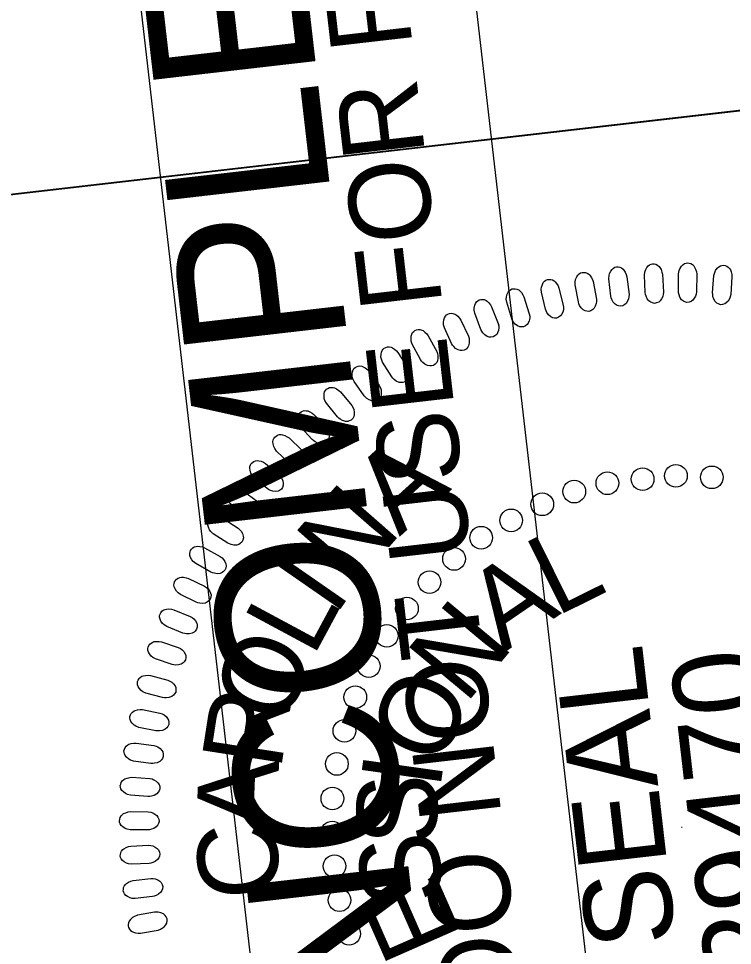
# Model space of a CAD drawing. Extents: x 477607 to 479438, y 495543 to 499482.
# Drawn here: x 477704.9 to 477755.3, y 497250.4 to 497316 of the extents above; entities that cross this region are included whole.
import ezdxf

# ---------------------------------------------------------------- set-up
doc = ezdxf.new("R2010")
doc.units = 0
for name, color, linetype in [('Sheet Border Standard 30in CELL', 7, 'Continuous'), ('Sheet PE Seal Cell', 7, 'Continuous'), ('Sheet Plan CELL', 7, 'Continuous'), ('Sheet Sticker Incomplete CELL', 7, 'Continuous')]:
    doc.layers.add(name, color=color, linetype=linetype)

msp = doc.modelspace()

# ---------------------------------------------------------------- linework, layer by layer
at = {"layer": 'Sheet Border Standard 30in CELL'}
msp.add_line((477682.369, 497301.002), (477794.079, 497313.883), dxfattribs=at)
for points in [[(477682.369, 497301.002), (477670.914, 497400.344), (477782.674, 497413.23), (477794.128, 497313.888)], [(477693.829, 497201.611), (477682.369, 497301.002), (477794.128, 497313.888), (477805.588, 497214.497)]]:
    msp.add_lwpolyline(points, close=True, dxfattribs=at)
at = {"layer": 'Sheet PE Seal Cell'}
msp.add_line((477751.702, 497258.805), (477751.748, 497258.81), dxfattribs=at)
for points in [[(477749.145, 497296.61), (477749.081, 497297.835), (477749.107, 497298.055), (477749.152, 497298.198), (477749.255, 497298.373), (477749.347, 497298.488), (477749.454, 497298.573), (477749.557, 497298.618), (477749.668, 497298.644), (477749.781, 497298.629), (477749.902, 497298.606), (477750.009, 497298.552), (477750.119, 497298.457), (477750.183, 497298.381), (477750.258, 497298.235), (477750.327, 497298.058), (477750.358, 497297.9), (477750.43, 497296.646), (477750.416, 497296.476), (477750.378, 497296.334), (477750.297, 497296.17), (477750.192, 497296.025), (477750.1, 497295.94), (477749.946, 497295.872), (477749.797, 497295.844), (477749.646, 497295.877), (477749.539, 497295.921), (477749.407, 497296.014), (477749.279, 497296.177), (477749.202, 497296.353), (477749.166, 497296.48)], [(477751.488, 497296.712), (477751.502, 497297.939), (477751.542, 497298.158), (477751.595, 497298.297), (477751.709, 497298.466), (477751.808, 497298.574), (477751.921, 497298.652), (477752.025, 497298.691), (477752.139, 497298.709), (477752.25, 497298.688), (477752.369, 497298.657), (477752.473, 497298.596), (477752.577, 497298.495), (477752.635, 497298.415), (477752.701, 497298.264), (477752.759, 497298.085), (477752.78, 497297.925), (477752.773, 497296.668), (477752.749, 497296.498), (477752.702, 497296.359), (477752.611, 497296.201), (477752.497, 497296.063), (477752.399, 497295.984), (477752.241, 497295.926), (477752.092, 497295.908), (477751.942, 497295.95), (477751.838, 497296), (477751.712, 497296.101), (477751.595, 497296.272), (477751.529, 497296.453), (477751.502, 497296.582)], [(477753.905, 497296.591), (477753.996, 497297.814), (477754.049, 497298.03), (477754.111, 497298.166), (477754.236, 497298.327), (477754.341, 497298.429), (477754.459, 497298.5), (477754.566, 497298.532), (477754.679, 497298.544), (477754.789, 497298.516), (477754.907, 497298.477), (477755.007, 497298.41), (477755.103, 497298.302), (477755.157, 497298.218), (477755.213, 497298.064), (477755.26, 497297.881), (477755.27, 497297.72), (477755.185, 497296.467), (477755.15, 497296.299), (477755.095, 497296.163), (477754.993, 497296.011), (477754.871, 497295.88), (477754.769, 497295.807), (477754.608, 497295.759), (477754.457, 497295.75), (477754.311, 497295.801), (477754.21, 497295.859), (477754.091, 497295.967), (477753.984, 497296.145), (477753.93, 497296.33), (477753.911, 497296.461)], [(477744.418, 497295.948), (477744.202, 497297.155), (477744.201, 497297.378), (477744.226, 497297.524), (477744.307, 497297.711), (477744.383, 497297.836), (477744.48, 497297.934), (477744.576, 497297.992), (477744.683, 497298.031), (477744.797, 497298.032), (477744.92, 497298.023), (477745.033, 497297.983), (477745.154, 497297.903), (477745.227, 497297.835), (477745.32, 497297.7), (477745.41, 497297.533), (477745.46, 497297.381), (477745.689, 497296.145), (477745.697, 497295.974), (477745.677, 497295.829), (477745.617, 497295.656), (477745.531, 497295.499), (477745.45, 497295.403), (477745.306, 497295.316), (477745.162, 497295.27), (477745.008, 497295.283), (477744.896, 497295.314), (477744.753, 497295.39), (477744.606, 497295.535), (477744.508, 497295.7), (477744.456, 497295.823)], [(477746.716, 497296.363), (477746.576, 497297.582), (477746.588, 497297.804), (477746.624, 497297.948), (477746.716, 497298.13), (477746.8, 497298.25), (477746.903, 497298.342), (477747.001, 497298.393), (477747.111, 497298.426), (477747.225, 497298.419), (477747.347, 497298.403), (477747.457, 497298.355), (477747.573, 497298.268), (477747.641, 497298.196), (477747.726, 497298.055), (477747.806, 497297.883), (477747.846, 497297.728), (477747.997, 497296.48), (477747.994, 497296.309), (477747.965, 497296.165), (477747.894, 497295.996), (477747.799, 497295.845), (477747.712, 497295.754), (477747.562, 497295.677), (477747.416, 497295.64), (477747.263, 497295.663), (477747.154, 497295.701), (477747.016, 497295.785), (477746.878, 497295.94), (477746.79, 497296.11), (477746.746, 497296.236)], [(477742.097, 497295.435), (477741.806, 497296.627), (477741.789, 497296.848), (477741.807, 497296.997), (477741.875, 497297.188), (477741.943, 497297.318), (477742.033, 497297.422), (477742.125, 497297.486), (477742.23, 497297.531), (477742.343, 497297.539), (477742.467, 497297.538), (477742.583, 497297.505), (477742.708, 497297.433), (477742.785, 497297.37), (477742.886, 497297.24), (477742.987, 497297.08), (477743.047, 497296.93), (477743.353, 497295.711), (477743.371, 497295.542), (477743.361, 497295.395), (477743.312, 497295.219), (477743.236, 497295.057), (477743.16, 497294.956), (477743.023, 497294.86), (477742.881, 497294.806), (477742.727, 497294.809), (477742.614, 497294.833), (477742.466, 497294.899), (477742.31, 497295.035), (477742.202, 497295.194), (477742.142, 497295.313)], [(477739.719, 497294.76), (477739.354, 497295.931), (477739.324, 497296.151), (477739.331, 497296.3), (477739.388, 497296.496), (477739.448, 497296.629), (477739.531, 497296.739), (477739.619, 497296.808), (477739.72, 497296.861), (477739.833, 497296.875), (477739.957, 497296.882), (477740.074, 497296.856), (477740.204, 497296.792), (477740.285, 497296.734), (477740.394, 497296.611), (477740.504, 497296.458), (477740.573, 497296.312), (477740.955, 497295.115), (477740.984, 497294.946), (477740.983, 497294.8), (477740.945, 497294.621), (477740.88, 497294.454), (477740.811, 497294.349), (477740.679, 497294.245), (477740.542, 497294.182), (477740.388, 497294.175), (477740.273, 497294.191), (477740.122, 497294.248), (477739.958, 497294.375), (477739.839, 497294.526), (477739.772, 497294.641)], [(477737.538, 497293.996), (477737.1, 497295.141), (477737.056, 497295.359), (477737.055, 497295.508), (477737.099, 497295.707), (477737.15, 497295.844), (477737.227, 497295.959), (477737.31, 497296.033), (477737.408, 497296.092), (477737.519, 497296.114), (477737.642, 497296.128), (477737.76, 497296.11), (477737.894, 497296.054), (477737.979, 497296.001), (477738.095, 497295.885), (477738.215, 497295.739), (477738.293, 497295.598), (477738.749, 497294.428), (477738.789, 497294.261), (477738.797, 497294.115), (477738.771, 497293.934), (477738.716, 497293.763), (477738.654, 497293.654), (477738.529, 497293.542), (477738.396, 497293.47), (477738.242, 497293.454), (477738.127, 497293.463), (477737.972, 497293.51), (477737.8, 497293.626), (477737.673, 497293.77), (477737.599, 497293.88)], [(477735.465, 497293.006), (477734.955, 497294.123), (477734.898, 497294.338), (477734.887, 497294.487), (477734.919, 497294.687), (477734.961, 497294.827), (477735.03, 497294.947), (477735.109, 497295.026), (477735.203, 497295.091), (477735.313, 497295.119), (477735.434, 497295.142), (477735.554, 497295.131), (477735.691, 497295.084), (477735.778, 497295.036), (477735.902, 497294.928), (477736.031, 497294.79), (477736.118, 497294.654), (477736.647, 497293.514), (477736.697, 497293.351), (477736.713, 497293.205), (477736.698, 497293.023), (477736.655, 497292.849), (477736.599, 497292.736), (477736.482, 497292.616), (477736.354, 497292.536), (477736.201, 497292.51), (477736.086, 497292.512), (477735.928, 497292.55), (477735.749, 497292.654), (477735.613, 497292.79), (477735.532, 497292.895)], [(477733.266, 497291.873), (477732.687, 497292.955), (477732.617, 497293.166), (477732.596, 497293.313), (477732.615, 497293.516), (477732.65, 497293.659), (477732.711, 497293.782), (477732.784, 497293.866), (477732.874, 497293.937), (477732.982, 497293.972), (477733.102, 497294.002), (477733.221, 497293.999), (477733.361, 497293.96), (477733.452, 497293.918), (477733.582, 497293.818), (477733.719, 497293.688), (477733.814, 497293.558), (477734.414, 497292.453), (477734.474, 497292.294), (477734.5, 497292.149), (477734.496, 497291.966), (477734.464, 497291.79), (477734.415, 497291.674), (477734.305, 497291.547), (477734.182, 497291.459), (477734.032, 497291.424), (477733.916, 497291.418), (477733.757, 497291.446), (477733.572, 497291.539), (477733.428, 497291.666), (477733.34, 497291.766)], [(477731.231, 497290.653), (477730.585, 497291.696), (477730.502, 497291.902), (477730.472, 497292.048), (477730.479, 497292.251), (477730.504, 497292.396), (477730.557, 497292.523), (477730.625, 497292.612), (477730.71, 497292.688), (477730.816, 497292.73), (477730.934, 497292.767), (477731.054, 497292.772), (477731.195, 497292.742), (477731.288, 497292.705), (477731.424, 497292.613), (477731.569, 497292.492), (477731.672, 497292.368), (477732.34, 497291.304), (477732.41, 497291.148), (477732.446, 497291.005), (477732.453, 497290.823), (477732.431, 497290.645), (477732.391, 497290.526), (477732.289, 497290.392), (477732.172, 497290.297), (477732.024, 497290.252), (477731.909, 497290.24), (477731.748, 497290.257), (477731.557, 497290.339), (477731.405, 497290.456), (477731.312, 497290.551)], [(477729.289, 497289.314), (477728.579, 497290.315), (477728.483, 497290.515), (477728.444, 497290.659), (477728.437, 497290.862), (477728.453, 497291.008), (477728.499, 497291.138), (477728.561, 497291.231), (477728.641, 497291.312), (477728.744, 497291.361), (477728.859, 497291.405), (477728.978, 497291.418), (477729.122, 497291.397), (477729.216, 497291.366), (477729.358, 497291.283), (477729.51, 497291.171), (477729.621, 497291.054), (477730.354, 497290.034), (477730.434, 497289.882), (477730.479, 497289.742), (477730.497, 497289.56), (477730.487, 497289.382), (477730.454, 497289.26), (477730.361, 497289.121), (477730.25, 497289.018), (477730.106, 497288.964), (477729.991, 497288.944), (477729.83, 497288.952), (477729.634, 497289.021), (477729.475, 497289.129), (477729.375, 497289.217)], [(477727.397, 497287.827), (477726.625, 497288.78), (477726.516, 497288.975), (477726.469, 497289.116), (477726.45, 497289.318), (477726.456, 497289.465), (477726.493, 497289.597), (477726.55, 497289.694), (477726.624, 497289.78), (477726.724, 497289.835), (477726.836, 497289.887), (477726.955, 497289.906), (477727.099, 497289.894), (477727.196, 497289.87), (477727.343, 497289.796), (477727.502, 497289.694), (477727.619, 497289.584), (477728.415, 497288.612), (477728.504, 497288.466), (477728.557, 497288.329), (477728.588, 497288.148), (477728.588, 497287.969), (477728.563, 497287.846), (477728.479, 497287.701), (477728.375, 497287.592), (477728.234, 497287.529), (477728.121, 497287.502), (477727.959, 497287.499), (477727.76, 497287.556), (477727.594, 497287.653), (477727.49, 497287.735)], [(477725.624, 497286.212), (477724.795, 497287.116), (477724.674, 497287.303), (477724.617, 497287.441), (477724.585, 497287.642), (477724.583, 497287.788), (477724.611, 497287.922), (477724.662, 497288.023), (477724.731, 497288.114), (477724.827, 497288.175), (477724.935, 497288.233), (477725.052, 497288.26), (477725.197, 497288.257), (477725.295, 497288.239), (477725.446, 497288.174), (477725.611, 497288.083), (477725.736, 497287.981), (477726.591, 497287.06), (477726.689, 497286.92), (477726.751, 497286.786), (477726.793, 497286.609), (477726.804, 497286.43), (477726.787, 497286.305), (477726.712, 497286.155), (477726.615, 497286.039), (477726.478, 497285.967), (477726.367, 497285.934), (477726.206, 497285.921), (477726.003, 497285.965), (477725.832, 497286.051), (477725.722, 497286.127)], [(477723.981, 497284.553), (477723.096, 497285.402), (477722.964, 497285.582), (477722.899, 497285.716), (477722.855, 497285.914), (477722.843, 497286.061), (477722.863, 497286.197), (477722.907, 497286.3), (477722.97, 497286.395), (477723.062, 497286.462), (477723.167, 497286.527), (477723.282, 497286.561), (477723.426, 497286.567), (477723.526, 497286.555), (477723.68, 497286.5), (477723.85, 497286.419), (477723.981, 497286.325), (477724.893, 497285.459), (477725, 497285.326), (477725.069, 497285.197), (477725.122, 497285.022), (477725.145, 497284.844), (477725.136, 497284.718), (477725.07, 497284.564), (477724.981, 497284.442), (477724.849, 497284.362), (477724.74, 497284.321), (477724.58, 497284.299), (477724.375, 497284.33), (477724.199, 497284.406), (477724.085, 497284.474)], [(477722.431, 497282.751), (477721.494, 497283.544), (477721.351, 497283.714), (477721.278, 497283.844), (477721.221, 497284.039), (477721.2, 497284.184), (477721.212, 497284.321), (477721.249, 497284.427), (477721.306, 497284.526), (477721.394, 497284.598), (477721.494, 497284.671), (477721.607, 497284.712), (477721.751, 497284.727), (477721.85, 497284.721), (477722.008, 497284.676), (477722.183, 497284.606), (477722.32, 497284.52), (477723.284, 497283.713), (477723.399, 497283.587), (477723.477, 497283.462), (477723.54, 497283.291), (477723.574, 497283.115), (477723.573, 497282.989), (477723.517, 497282.831), (477723.435, 497282.704), (477723.309, 497282.615), (477723.203, 497282.568), (477723.045, 497282.535), (477722.838, 497282.554), (477722.657, 497282.618), (477722.539, 497282.679)], [(477720.948, 497280.824), (477719.964, 497281.557), (477719.81, 497281.717), (477719.729, 497281.843), (477719.66, 497282.034), (477719.63, 497282.178), (477719.633, 497282.315), (477719.663, 497282.423), (477719.714, 497282.525), (477719.797, 497282.603), (477719.893, 497282.681), (477720.003, 497282.729), (477720.145, 497282.754), (477720.246, 497282.754), (477720.406, 497282.719), (477720.585, 497282.66), (477720.726, 497282.583), (477721.739, 497281.838), (477721.862, 497281.719), (477721.947, 497281.6), (477722.021, 497281.433), (477722.067, 497281.26), (477722.073, 497281.134), (477722.027, 497280.972), (477721.954, 497280.84), (477721.832, 497280.745), (477721.73, 497280.69), (477721.574, 497280.648), (477721.367, 497280.653), (477721.183, 497280.706), (477721.061, 497280.76)], [(477719.647, 497278.891), (477718.619, 497279.56), (477718.455, 497279.711), (477718.367, 497279.831), (477718.285, 497280.017), (477718.246, 497280.158), (477718.241, 497280.296), (477718.264, 497280.405), (477718.309, 497280.511), (477718.386, 497280.594), (477718.477, 497280.678), (477718.584, 497280.733), (477718.725, 497280.766), (477718.824, 497280.773), (477718.986, 497280.747), (477719.17, 497280.7), (477719.316, 497280.632), (477720.373, 497279.953), (477720.503, 497279.841), (477720.596, 497279.727), (477720.68, 497279.566), (477720.737, 497279.395), (477720.751, 497279.27), (477720.715, 497279.106), (477720.65, 497278.97), (477720.535, 497278.866), (477720.436, 497278.806), (477720.283, 497278.754), (477720.076, 497278.746), (477719.888, 497278.788), (477719.764, 497278.833)], [(477718.457, 497276.847), (477717.389, 497277.45), (477717.216, 497277.59), (477717.12, 497277.705), (477717.027, 497277.885), (477716.98, 497278.024), (477716.965, 497278.16), (477716.982, 497278.272), (477717.02, 497278.379), (477717.092, 497278.467), (477717.177, 497278.556), (477717.28, 497278.618), (477717.419, 497278.66), (477717.518, 497278.673), (477717.681, 497278.658), (477717.867, 497278.622), (477718.017, 497278.563), (477719.115, 497277.952), (477719.251, 497277.849), (477719.351, 497277.741), (477719.446, 497277.585), (477719.513, 497277.418), (477719.534, 497277.294), (477719.509, 497277.129), (477719.453, 497276.989), (477719.345, 497276.878), (477719.25, 497276.811), (477719.101, 497276.749), (477718.894, 497276.729), (477718.705, 497276.759), (477718.577, 497276.796)], [(477717.421, 497274.715), (477716.317, 497275.249), (477716.136, 497275.378), (477716.034, 497275.486), (477715.929, 497275.661), (477715.873, 497275.796), (477715.85, 497275.932), (477715.86, 497276.043), (477715.891, 497276.154), (477715.958, 497276.246), (477716.037, 497276.34), (477716.136, 497276.408), (477716.272, 497276.459), (477716.37, 497276.478), (477716.534, 497276.473), (477716.721, 497276.449), (477716.875, 497276.4), (477718.009, 497275.859), (477718.151, 497275.764), (477718.257, 497275.663), (477718.362, 497275.513), (477718.439, 497275.352), (477718.469, 497275.229), (477718.454, 497275.061), (477718.406, 497274.918), (477718.306, 497274.801), (477718.215, 497274.729), (477718.07, 497274.657), (477717.865, 497274.624), (477717.674, 497274.642), (477717.545, 497274.672)], [(477716.48, 497272.534), (477715.345, 497272.998), (477715.156, 497273.116), (477715.046, 497273.217), (477714.932, 497273.385), (477714.867, 497273.517), (477714.836, 497273.651), (477714.838, 497273.763), (477714.862, 497273.874), (477714.923, 497273.97), (477714.996, 497274.069), (477715.091, 497274.144), (477715.223, 497274.203), (477715.319, 497274.228), (477715.483, 497274.234), (477715.672, 497274.221), (477715.828, 497274.182), (477716.994, 497273.713), (477717.143, 497273.628), (477717.255, 497273.534), (477717.369, 497273.391), (477717.456, 497273.233), (477717.493, 497273.113), (477717.489, 497272.945), (477717.451, 497272.799), (477717.357, 497272.676), (477717.271, 497272.598), (477717.13, 497272.518), (477716.929, 497272.472), (477716.737, 497272.477), (477716.605, 497272.499)], [(477715.714, 497270.308), (477714.552, 497270.7), (477714.356, 497270.805), (477714.241, 497270.9), (477714.116, 497271.06), (477714.043, 497271.187), (477714.003, 497271.319), (477713.999, 497271.431), (477714.016, 497271.544), (477714.071, 497271.643), (477714.137, 497271.747), (477714.227, 497271.827), (477714.356, 497271.894), (477714.45, 497271.926), (477714.614, 497271.942), (477714.802, 497271.941), (477714.961, 497271.911), (477716.154, 497271.517), (477716.307, 497271.441), (477716.426, 497271.354), (477716.548, 497271.218), (477716.644, 497271.067), (477716.689, 497270.949), (477716.696, 497270.781), (477716.666, 497270.633), (477716.581, 497270.505), (477716.501, 497270.422), (477716.365, 497270.333), (477716.167, 497270.274), (477715.975, 497270.267), (477715.843, 497270.281)], [(477715.043, 497267.974), (477713.859, 497268.293), (477713.657, 497268.386), (477713.535, 497268.472), (477713.401, 497268.625), (477713.32, 497268.747), (477713.272, 497268.876), (477713.261, 497268.987), (477713.27, 497269.101), (477713.319, 497269.204), (477713.379, 497269.312), (477713.464, 497269.397), (477713.587, 497269.473), (477713.68, 497269.51), (477713.841, 497269.536), (477714.03, 497269.547), (477714.19, 497269.527), (477715.406, 497269.208), (477715.564, 497269.142), (477715.687, 497269.063), (477715.817, 497268.935), (477715.924, 497268.791), (477715.976, 497268.676), (477715.992, 497268.509), (477715.973, 497268.359), (477715.896, 497268.225), (477715.82, 497268.137), (477715.691, 497268.04), (477715.496, 497267.969), (477715.305, 497267.95), (477715.172, 497267.955)], [(477714.575, 497265.622), (477713.372, 497265.865), (477713.165, 497265.946), (477713.039, 497266.024), (477712.894, 497266.168), (477712.806, 497266.285), (477712.75, 497266.41), (477712.732, 497266.521), (477712.735, 497266.635), (477712.776, 497266.741), (477712.83, 497266.852), (477712.909, 497266.943), (477713.027, 497267.025), (477713.117, 497267.068), (477713.277, 497267.105), (477713.465, 497267.128), (477713.626, 497267.118), (477714.859, 497266.876), (477715.021, 497266.821), (477715.149, 497266.749), (477715.288, 497266.629), (477715.402, 497266.491), (477715.461, 497266.381), (477715.489, 497266.215), (477715.478, 497266.064), (477715.41, 497265.926), (477715.34, 497265.833), (477715.217, 497265.728), (477715.027, 497265.645), (477714.838, 497265.614), (477714.705, 497265.611)], [(477714.215, 497263.316), (477713, 497263.483), (477712.788, 497263.55), (477712.656, 497263.621), (477712.503, 497263.755), (477712.408, 497263.866), (477712.344, 497263.988), (477712.319, 497264.097), (477712.314, 497264.211), (477712.349, 497264.319), (477712.395, 497264.434), (477712.469, 497264.529), (477712.582, 497264.619), (477712.669, 497264.667), (477712.827, 497264.714), (477713.013, 497264.749), (477713.174, 497264.75), (477714.42, 497264.585), (477714.584, 497264.539), (477714.717, 497264.476), (477714.862, 497264.365), (477714.986, 497264.235), (477715.052, 497264.128), (477715.089, 497263.965), (477715.088, 497263.814), (477715.028, 497263.671), (477714.965, 497263.574), (477714.849, 497263.462), (477714.665, 497263.366), (477714.477, 497263.325), (477714.345, 497263.312)], [(477714.008, 497260.971), (477712.785, 497261.062), (477712.569, 497261.115), (477712.434, 497261.178), (477712.273, 497261.302), (477712.171, 497261.407), (477712.099, 497261.525), (477712.067, 497261.632), (477712.055, 497261.746), (477712.084, 497261.856), (477712.122, 497261.973), (477712.19, 497262.073), (477712.297, 497262.17), (477712.381, 497262.223), (477712.535, 497262.28), (477712.719, 497262.326), (477712.88, 497262.337), (477714.133, 497262.251), (477714.3, 497262.216), (477714.436, 497262.161), (477714.589, 497262.06), (477714.72, 497261.938), (477714.792, 497261.835), (477714.84, 497261.674), (477714.849, 497261.523), (477714.798, 497261.377), (477714.741, 497261.277), (477714.632, 497261.157), (477714.454, 497261.051), (477714.27, 497260.997), (477714.138, 497260.977)], [(477713.991, 497258.614), (477712.765, 497258.628), (477712.545, 497258.668), (477712.407, 497258.722), (477712.239, 497258.836), (477712.13, 497258.934), (477712.052, 497259.048), (477712.012, 497259.152), (477711.994, 497259.264), (477712.016, 497259.377), (477712.046, 497259.495), (477712.108, 497259.6), (477712.209, 497259.703), (477712.289, 497259.762), (477712.439, 497259.828), (477712.62, 497259.885), (477712.779, 497259.906), (477714.036, 497259.9), (477714.205, 497259.875), (477714.344, 497259.829), (477714.503, 497259.737), (477714.641, 497259.624), (477714.72, 497259.526), (477714.778, 497259.368), (477714.796, 497259.218), (477714.754, 497259.069), (477714.704, 497258.965), (477714.602, 497258.839), (477714.431, 497258.721), (477714.251, 497258.656), (477714.121, 497258.628)], [(477714.088, 497256.247), (477712.863, 497256.184), (477712.642, 497256.21), (477712.5, 497256.255), (477712.325, 497256.358), (477712.21, 497256.45), (477712.124, 497256.557), (477712.08, 497256.66), (477712.054, 497256.771), (477712.068, 497256.884), (477712.092, 497257.005), (477712.146, 497257.113), (477712.24, 497257.222), (477712.317, 497257.286), (477712.463, 497257.361), (477712.639, 497257.43), (477712.797, 497257.461), (477714.052, 497257.533), (477714.222, 497257.52), (477714.364, 497257.482), (477714.527, 497257.4), (477714.673, 497257.296), (477714.758, 497257.203), (477714.826, 497257.049), (477714.854, 497256.9), (477714.821, 497256.749), (477714.776, 497256.642), (477714.683, 497256.51), (477714.521, 497256.382), (477714.345, 497256.305), (477714.216, 497256.269)], [(477714.332, 497253.901), (477713.113, 497253.76), (477712.891, 497253.773), (477712.746, 497253.809), (477712.565, 497253.901), (477712.445, 497253.985), (477712.353, 497254.087), (477712.301, 497254.186), (477712.269, 497254.296), (477712.276, 497254.409), (477712.292, 497254.532), (477712.339, 497254.642), (477712.426, 497254.758), (477712.499, 497254.826), (477712.64, 497254.91), (477712.811, 497254.99), (477712.967, 497255.031), (477714.215, 497255.181), (477714.386, 497255.179), (477714.53, 497255.15), (477714.698, 497255.079), (477714.85, 497254.984), (477714.94, 497254.896), (477715.018, 497254.747), (477715.054, 497254.601), (477715.032, 497254.448), (477714.995, 497254.338), (477714.91, 497254.2), (477714.755, 497254.062), (477714.584, 497253.975), (477714.459, 497253.93)], [(477714.469, 497252.794), (477713.261, 497252.577), (477713.052, 497252.502), (477712.924, 497252.426), (477712.776, 497252.285), (477712.685, 497252.171), (477712.627, 497252.046), (477712.606, 497251.936), (477712.606, 497251.822), (477712.646, 497251.715), (477712.696, 497251.603), (477712.773, 497251.51), (477712.89, 497251.425), (477712.979, 497251.381), (477713.138, 497251.34), (477713.326, 497251.313), (477713.486, 497251.319), (477714.725, 497251.534), (477714.888, 497251.585), (477715.017, 497251.654), (477715.159, 497251.77), (477715.276, 497251.906), (477715.338, 497252.015), (477715.369, 497252.181), (477715.362, 497252.331), (477715.296, 497252.472), (477715.229, 497252.566), (477715.108, 497252.673), (477714.92, 497252.761), (477714.731, 497252.795), (477714.599, 497252.802)]]:
    msp.add_lwpolyline(points, close=True, dxfattribs=at)
for centre in [(477748.961, 497283.412), (477751.313, 497283.653), (477753.852, 497283.544), (477746.468, 497283.125), (477744.13, 497282.536), (477741.868, 497281.635), (477739.672, 497280.501), (477737.549, 497279.277), (477735.637, 497277.775), (477733.901, 497276.132), (477732.311, 497274.266), (477730.888, 497272.34), (477729.612, 497270.189), (477728.661, 497267.996), (477727.891, 497265.623), (477727.359, 497263.278), (477727.038, 497260.836), (477727.034, 497258.431), (477727.188, 497256.044), (477727.544, 497253.641), (477728.218, 497251.273)]:
    msp.add_circle(centre, 0.801, dxfattribs=at)
at = {"layer": 'Sheet Plan CELL'}
msp.add_line((477682.38, 497301.016), (477794.101, 497313.91), dxfattribs=at)
for points in [[(477682.38, 497301.016), (477670.914, 497400.344), (477782.685, 497413.244), (477794.152, 497313.904)], [(477693.84, 497201.625), (477682.38, 497301.016), (477794.152, 497313.904), (477805.585, 497214.522)]]:
    msp.add_lwpolyline(points, close=True, dxfattribs=at)
at = {"layer": 'Sheet Sticker Incomplete CELL'}
msp.add_lwpolyline([(477746.678, 497234.443), (477723.333, 497231.751), (477706.495, 497377.784), (477729.84, 497380.475)], close=True, dxfattribs=at)

# ---------------------------------------------------------------- texts
at = {"layer": 'Sheet PE Seal Cell'}
for s, height, rotation, p in [('A', 5.669, 42.25011, (477731.781, 497279.329)), ('N', 5.669, 48.73947, (477728.406, 497275.598)), ('L', 5.669, 26.40814, (477742.836, 497273.666)), ('I', 5.669, 55.22882, (477727.202, 497273.642)), ('A', 5.669, 34.34794, (477739.111, 497271.099)), ('L', 5.669, 61.71818, (477725.669, 497270.755)), ('N', 5.669, 50.22753, (477736.432, 497267.431)), ('O', 5.669, 68.20754, (477723.697, 497265.763)), ('SEAL', 6.2363, 96.55865, (477751.338, 497250.668)), ('29470', 6.2363, 96.55865, (477759.704, 497248.641)), ('O', 5.669, 66.10713, (477734.637, 497262.884)), ('R', 5.669, 81.18625, (477723.386, 497262.753)), ('A', 5.669, 87.67561, (477723.078, 497258.483)), ('I', 5.669, 81.98672, (477734.639, 497261.37)), ('S', 5.669, 89.92652, (477734.447, 497257.523)), ('C', 5.669, 94.16496, (477723.396, 497253.914)), ('S', 5.669, 97.86632, (477734.989, 497253.699)), ('E', 5.669, 113.74591, (477736.26, 497251.06))]:
    msp.add_text(s, height=height, rotation=rotation, dxfattribs=at).set_placement(p)
at = {"layer": 'Sheet Sticker Incomplete CELL'}
for s, height, p in [('INCOMPLETE PLANS', 11.52, (477734.03, 497241.994)), ('DO NOT USE FOR R/W ACQUISITION', 5.76, (477740.562, 497246.018))]:
    msp.add_text(s, height=height, rotation=96.57729, dxfattribs=at).set_placement(p)

doc.saveas('drawing.dxf')
